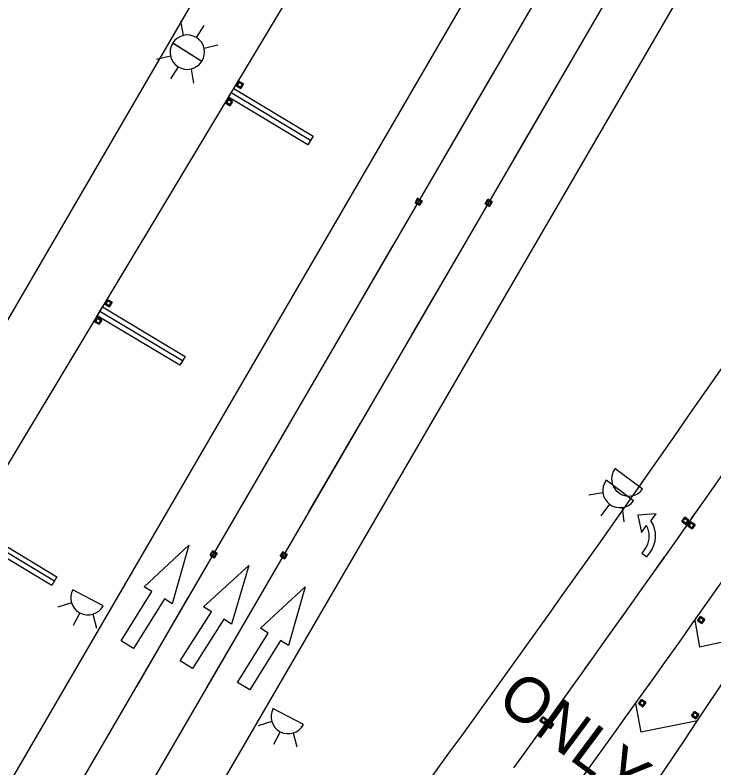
# Model space of a CAD drawing. Extents: x 2471014 to 2497726, y 6959577 to 6980268.
# Drawn here: x 2488749.7 to 2488886.8, y 6964487 to 6964634.8 of the extents above; entities that cross this region are included whole.
import ezdxf

# ---------------------------------------------------------------- set-up
doc = ezdxf.new("R2010")
doc.units = 0
for name, color, linetype in [('13', 7, 'Continuous'), ('18', 7, 'Continuous'), ('23', 7, 'Continuous'), ('25', 7, 'Continuous'), ('59', 7, 'Continuous'), ('ALIGN_ML_IH35_NB_SB', 7, 'Continuous'), ('G-GRID-MAJR', 7, 'Continuous'), ('Level 30', 7, 'Continuous'), ('Level 40', 7, 'Continuous'), ('p_structure fence', 7, 'Continuous'), ('p_structure wall', 7, 'Continuous'), ('PMK_Del_D-SW_SZ_TYC_CTB_BI', 7, 'Continuous'), ('PMK_Del_D-SY_SZ_TYC_CTB', 7, 'Continuous'), ('PMK_Pav_Marker_TY I C', 7, 'Continuous'), ('RDWY_PAVE_XSTREET_FOC', 7, 'Continuous'), ('S-BRDG-DECK', 7, 'Continuous'), ('SHADE SW', 7, 'Continuous'), ('V7_25', 7, 'Continuous')]:
    doc.layers.add(name, color=color, linetype=linetype)

msp = doc.modelspace()

# ---------------------------------------------------------------- linework, layer by layer
at = {"layer": '13'}
msp.add_line((2488620.75, 6964263.98), (2489501.89, 6965780.24), dxfattribs=at)
msp.add_arc((2485597.1, 6966838.82), 4000, 322.02534, 329.83805, dxfattribs=at)
at = {"layer": '18'}
for p, q in [((2488642.18, 6964392.39), (2489501.29, 6965870.76)), ((2488735.14, 6964389.16), (2489533.02, 6965762.15)), ((2488737.13, 6964527.93), (2489107.54, 6965145.42))]:
    msp.add_line(p, q, dxfattribs=at)
at = {"layer": '23'}
for p, q in [((2488828.16, 6964597.98), (2488828.67, 6964598.86)), ((2488829.54, 6964598.35), (2488828.67, 6964598.86)), ((2488828.67, 6964598.86), (2488828.72, 6964598.63)), ((2488828.72, 6964598.63), (2488828.84, 6964598.56)), ((2488828.84, 6964598.56), (2488829.3, 6964598.29)), ((2488841.91, 6964597.77), (2488842.42, 6964598.65)), ((2488843.3, 6964598.14), (2488842.42, 6964598.65)), ((2488842.42, 6964598.65), (2488842.47, 6964598.42)), ((2488828.38, 6964598.05), (2488828.16, 6964597.98)), ((2488828.16, 6964597.98), (2488828.39, 6964597.85)), ((2488828.96, 6964597.71), (2488828.38, 6964598.05)), ((2488828.39, 6964597.85), (2488829.03, 6964597.47)), ((2488829.03, 6964597.47), (2488828.96, 6964597.71)), ((2488829.54, 6964598.35), (2488829.03, 6964597.47)), ((2488829.3, 6964598.29), (2488829.54, 6964598.35)), ((2488842.13, 6964597.83), (2488841.91, 6964597.77)), ((2488841.91, 6964597.77), (2488842.14, 6964597.63)), ((2488842.72, 6964597.49), (2488842.13, 6964597.83)), ((2488842.14, 6964597.63), (2488842.79, 6964597.26)), ((2488842.47, 6964598.42), (2488842.6, 6964598.35)), ((2488842.6, 6964598.35), (2488843.06, 6964598.08)), ((2488842.79, 6964597.26), (2488842.72, 6964597.49)), ((2488843.3, 6964598.14), (2488842.79, 6964597.26)), ((2488843.06, 6964598.08), (2488843.3, 6964598.14)), ((2488880.46, 6964535.41), (2488881.04, 6964536.24)), ((2488880.68, 6964535.46), (2488880.46, 6964535.41)), ((2488880.46, 6964535.41), (2488880.68, 6964535.26)), ((2488881.24, 6964535.07), (2488880.68, 6964535.46)), ((2488880.68, 6964535.26), (2488881.29, 6964534.83)), ((2488881.87, 6964535.66), (2488881.04, 6964536.24)), ((2488881.04, 6964536.24), (2488881.07, 6964536.01)), ((2488881.07, 6964536.01), (2488881.19, 6964535.93)), ((2488881.19, 6964535.93), (2488881.63, 6964535.62)), ((2488881.29, 6964534.83), (2488881.24, 6964535.07)), ((2488881.87, 6964535.66), (2488881.29, 6964534.83)), ((2488881.63, 6964535.62), (2488881.87, 6964535.66)), ((2488881.67, 6964534.53), (2488882.25, 6964535.37)), ((2488883.08, 6964534.78), (2488882.25, 6964535.37)), ((2488882.25, 6964535.37), (2488882.29, 6964535.13)), ((2488882.29, 6964535.13), (2488882.4, 6964535.05)), ((2488882.4, 6964535.05), (2488882.84, 6964534.75)), ((2488881.9, 6964534.58), (2488881.67, 6964534.53)), ((2488881.67, 6964534.53), (2488881.89, 6964534.38)), ((2488881.89, 6964534.38), (2488882.5, 6964533.95)), ((2488882.45, 6964534.19), (2488881.9, 6964534.58)), ((2488882.5, 6964533.95), (2488882.45, 6964534.19)), ((2488883.08, 6964534.78), (2488882.5, 6964533.95)), ((2488882.84, 6964534.75), (2488883.08, 6964534.78)), ((2488787.96, 6964528.81), (2488788.47, 6964529.69)), ((2488789.35, 6964529.18), (2488788.47, 6964529.69)), ((2488788.47, 6964529.69), (2488788.52, 6964529.46)), ((2488788.52, 6964529.46), (2488788.65, 6964529.39)), ((2488788.65, 6964529.39), (2488789.11, 6964529.12)), ((2488789.35, 6964529.18), (2488788.84, 6964528.3)), ((2488789.11, 6964529.12), (2488789.35, 6964529.18)), ((2488801.71, 6964528.6), (2488802.23, 6964529.48)), ((2488803.1, 6964528.97), (2488802.23, 6964529.48)), ((2488802.23, 6964529.48), (2488802.28, 6964529.25)), ((2488802.28, 6964529.25), (2488802.4, 6964529.18)), ((2488802.4, 6964529.18), (2488802.86, 6964528.91)), ((2488788.18, 6964528.88), (2488787.96, 6964528.81)), ((2488787.96, 6964528.81), (2488788.19, 6964528.68)), ((2488788.77, 6964528.54), (2488788.18, 6964528.88)), ((2488788.19, 6964528.68), (2488788.84, 6964528.3)), ((2488788.84, 6964528.3), (2488788.77, 6964528.54)), ((2488801.94, 6964528.66), (2488801.71, 6964528.6)), ((2488801.71, 6964528.6), (2488801.95, 6964528.46)), ((2488802.52, 6964528.32), (2488801.94, 6964528.66)), ((2488801.95, 6964528.46), (2488802.59, 6964528.09)), ((2488802.59, 6964528.09), (2488802.52, 6964528.32)), ((2488803.1, 6964528.97), (2488802.59, 6964528.09)), ((2488802.86, 6964528.91), (2488803.1, 6964528.97)), ((2488883.58, 6964515.97), (2488884.16, 6964516.79)), ((2488883.81, 6964516.01), (2488883.58, 6964515.97)), ((2488883.58, 6964515.97), (2488883.8, 6964515.81)), ((2488883.8, 6964515.81), (2488884.41, 6964515.38)), ((2488884.36, 6964515.62), (2488883.81, 6964516.01)), ((2488884.99, 6964516.21), (2488884.16, 6964516.79)), ((2488884.16, 6964516.79), (2488884.2, 6964516.56)), ((2488884.2, 6964516.56), (2488884.31, 6964516.48)), ((2488884.31, 6964516.48), (2488884.75, 6964516.17)), ((2488884.99, 6964516.21), (2488884.41, 6964515.38)), ((2488884.75, 6964516.17), (2488884.99, 6964516.21)), ((2488884.41, 6964515.38), (2488884.36, 6964515.62)), ((2488872, 6964499.66), (2488872.59, 6964500.49)), ((2488872.22, 6964499.71), (2488872, 6964499.66)), ((2488872, 6964499.66), (2488872.21, 6964499.51)), ((2488872.21, 6964499.51), (2488872.82, 6964499.07)), ((2488872.77, 6964499.31), (2488872.22, 6964499.71)), ((2488873.41, 6964499.9), (2488872.59, 6964500.49)), ((2488872.59, 6964500.49), (2488872.62, 6964500.26)), ((2488872.62, 6964500.26), (2488872.73, 6964500.18)), ((2488872.73, 6964500.18), (2488873.17, 6964499.87)), ((2488873.41, 6964499.9), (2488872.82, 6964499.07)), ((2488873.17, 6964499.87), (2488873.41, 6964499.9)), ((2488872.82, 6964499.07), (2488872.77, 6964499.31)), ((2488882.38, 6964497.27), (2488882.94, 6964498.12)), ((2488883.79, 6964497.56), (2488882.94, 6964498.12)), ((2488882.94, 6964498.12), (2488882.98, 6964497.89)), ((2488852.66, 6964496.29), (2488853.25, 6964497.11)), ((2488854.07, 6964496.52), (2488853.25, 6964497.11)), ((2488853.25, 6964497.11), (2488853.28, 6964496.88)), ((2488853.28, 6964496.88), (2488853.4, 6964496.8)), ((2488853.4, 6964496.8), (2488853.83, 6964496.49)), ((2488882.61, 6964497.33), (2488882.38, 6964497.27)), ((2488882.38, 6964497.27), (2488882.6, 6964497.12)), ((2488882.6, 6964497.12), (2488883.23, 6964496.71)), ((2488883.17, 6964496.95), (2488882.61, 6964497.33)), ((2488882.98, 6964497.89), (2488883.1, 6964497.81)), ((2488883.1, 6964497.81), (2488883.54, 6964497.52)), ((2488883.23, 6964496.71), (2488883.17, 6964496.95)), ((2488883.79, 6964497.56), (2488883.23, 6964496.71)), ((2488883.54, 6964497.52), (2488883.79, 6964497.56)), ((2488852.89, 6964496.33), (2488852.66, 6964496.29)), ((2488852.66, 6964496.29), (2488852.88, 6964496.13)), ((2488852.88, 6964496.13), (2488853.48, 6964495.7)), ((2488853.44, 6964495.94), (2488852.89, 6964496.33)), ((2488853.48, 6964495.7), (2488853.44, 6964495.94)), ((2488854.07, 6964496.52), (2488853.48, 6964495.7)), ((2488853.83, 6964496.49), (2488854.07, 6964496.52)), ((2488853.87, 6964495.41), (2488854.47, 6964496.23)), ((2488854.1, 6964495.45), (2488853.87, 6964495.41)), ((2488853.87, 6964495.41), (2488854.09, 6964495.25)), ((2488854.09, 6964495.25), (2488854.7, 6964494.82)), ((2488854.65, 6964495.06), (2488854.1, 6964495.45)), ((2488855.29, 6964495.64), (2488854.47, 6964496.23)), ((2488854.47, 6964496.23), (2488854.5, 6964496)), ((2488854.5, 6964496), (2488854.61, 6964495.92)), ((2488854.61, 6964495.92), (2488855.05, 6964495.61)), ((2488854.7, 6964494.82), (2488854.65, 6964495.06)), ((2488855.29, 6964495.64), (2488854.7, 6964494.82)), ((2488855.05, 6964495.61), (2488855.29, 6964495.64))]:
    msp.add_line(p, q, dxfattribs=at)
for points in [[(2488828.38, 6964598.05), (2488828.72, 6964598.63), (2488829.3, 6964598.29), (2488828.96, 6964597.71)], [(2488842.13, 6964597.83), (2488842.47, 6964598.42), (2488843.06, 6964598.08), (2488842.72, 6964597.49)], [(2488880.68, 6964535.46), (2488881.07, 6964536.01), (2488881.63, 6964535.62), (2488881.24, 6964535.07)], [(2488881.9, 6964534.58), (2488882.29, 6964535.13), (2488882.84, 6964534.75), (2488882.45, 6964534.19)], [(2488788.18, 6964528.88), (2488788.52, 6964529.46), (2488789.11, 6964529.12), (2488788.77, 6964528.54)], [(2488801.94, 6964528.66), (2488802.28, 6964529.25), (2488802.86, 6964528.91), (2488802.52, 6964528.32)], [(2488883.81, 6964516.01), (2488884.2, 6964516.56), (2488884.75, 6964516.17), (2488884.36, 6964515.62)], [(2488872.22, 6964499.71), (2488872.62, 6964500.26), (2488873.17, 6964499.87), (2488872.77, 6964499.31)], [(2488852.89, 6964496.33), (2488853.28, 6964496.88), (2488853.83, 6964496.49), (2488853.44, 6964495.94)], [(2488882.61, 6964497.33), (2488882.98, 6964497.89), (2488883.54, 6964497.52), (2488883.17, 6964496.95)], [(2488854.1, 6964495.45), (2488854.5, 6964496), (2488855.05, 6964495.61), (2488854.65, 6964495.06)]]:
    msp.add_lwpolyline(points, close=True, dxfattribs=at)
at = {"layer": '25'}
for centre, radius, start, end in [((2485597.1, 6966838.82), 4024, 324.04653, 328.03154), ((2487228.94, 6965594.72), 1986, 322.75841, 329.83805), ((2487228.94, 6965594.72), 2000, 322.75857, 329.83805)]:
    msp.add_arc(centre, radius, start, end, dxfattribs=at)
at = {"layer": '59'}
msp.add_arc((2485597.1, 6966838.82), 4012, 324.11333, 329.83805, dxfattribs=at)
at = {"layer": 'ALIGN_ML_IH35_NB_SB'}
for p, q in [((2488775.04, 6964522.61), (2488783.81, 6964530.79)), ((2488783.81, 6964530.79), (2488780.52, 6964519.27)), ((2488786.69, 6964518.65), (2488795.54, 6964526.75)), ((2488795.54, 6964526.75), (2488792.14, 6964515.26)), ((2488770.55, 6964512.01), (2488776.56, 6964521.66)), ((2488776.56, 6964521.66), (2488775.04, 6964522.61)), ((2488797.83, 6964514.45), (2488806.61, 6964522.62)), ((2488806.61, 6964522.62), (2488803.31, 6964511.1)), ((2488778.99, 6964520.22), (2488772.95, 6964510.52)), ((2488780.52, 6964519.27), (2488778.99, 6964520.22)), ((2488782.11, 6964508.09), (2488788.21, 6964517.69)), ((2488788.21, 6964517.69), (2488786.69, 6964518.65)), ((2488790.63, 6964516.22), (2488784.49, 6964506.58)), ((2488792.14, 6964515.26), (2488790.63, 6964516.22)), ((2488799.36, 6964513.5), (2488797.83, 6964514.45)), ((2488793.34, 6964503.85), (2488799.36, 6964513.5)), ((2488772.95, 6964510.52), (2488770.55, 6964512.01)), ((2488801.78, 6964512.06), (2488795.73, 6964502.36)), ((2488803.31, 6964511.1), (2488801.78, 6964512.06)), ((2488784.49, 6964506.58), (2488782.11, 6964508.09)), ((2488795.73, 6964502.36), (2488793.34, 6964503.85))]:
    msp.add_line(p, q, dxfattribs=at)
at = {"layer": 'G-GRID-MAJR'}
for p, q in [((2488791.57, 6964618.68), (2488792.6, 6964620.4)), ((2488792.6, 6964620.4), (2488808.19, 6964611.04)), ((2488807.16, 6964609.33), (2488791.57, 6964618.68)), ((2488808.19, 6964611.04), (2488807.16, 6964609.33)), ((2488765.85, 6964575.8), (2488766.88, 6964577.52)), ((2488766.88, 6964577.52), (2488783.07, 6964567.81)), ((2488782.04, 6964566.09), (2488765.85, 6964575.8)), ((2488783.07, 6964567.81), (2488782.04, 6964566.09)), ((2488741.16, 6964534.64), (2488757.94, 6964524.57)), ((2488756.91, 6964522.86), (2488740.13, 6964532.93)), ((2488757.94, 6964524.57), (2488756.91, 6964522.86)), ((2488883, 6964516.02), (2488883.97, 6964510.77)), ((2488894.52, 6964513.02), (2488883.97, 6964510.77)), ((2488871.41, 6964499.71), (2488872.43, 6964494.05)), ((2488883.55, 6964496.3), (2488872.43, 6964494.05))]:
    msp.add_line(p, q, dxfattribs=at)
at = {"layer": 'Level 30'}
for p, q in [((2488806.26, 6964495.56), (2488800.29, 6964498.72)), ((2488800.05, 6964496.15), (2488797.37, 6964495.29)), ((2488801.7, 6964494.16), (2488800.38, 6964491.67)), ((2488804.27, 6964493.92), (2488804.99, 6964491.2))]:
    msp.add_line(p, q, dxfattribs=at)
msp.add_arc((2488803.28, 6964497.14), 3.37, 152.0959, 332.0959, dxfattribs=at)
at = {"layer": 'Level 40'}
for p, q in [((2488882.34, 6964535.92), (2488884.06, 6964538.38)), ((2488875.43, 6964526.11), (2488877.16, 6964528.56)), ((2488868.5, 6964516.31), (2488870.24, 6964518.76)), ((2488861.54, 6964506.54), (2488863.28, 6964508.98)), ((2488854.55, 6964496.78), (2488856.3, 6964499.22)), ((2488847.53, 6964487.05), (2488849.29, 6964489.48))]:
    msp.add_line(p, q, dxfattribs=at)
at = {"layer": 'p_structure wall'}
for p, q in [((2488875.47, 6964536.94), (2488871.87, 6964536.69)), ((2488871.87, 6964536.69), (2488872.57, 6964533.27)), ((2488874.43, 6964535.57), (2488875.47, 6964536.94)), ((2488872.57, 6964533.27), (2488873.58, 6964534.6)), ((2488873.23, 6964530), (2488872.63, 6964529.21)), ((2488872.63, 6964529.21), (2488873.61, 6964528.47)), ((2488873.61, 6964528.47), (2488874.21, 6964529.25))]:
    msp.add_line(p, q, dxfattribs=at)
for radius, start, end in [(5.49, 322.8479, 33.1373), (4.26, 330.7191, 28.4617), (4.26, 322.889, 328.4717), (4.26, 328.4717, 330.7191)]:
    msp.add_arc((2488869.83, 6964532.57), radius, start, end, dxfattribs=at)
at = {"layer": 'PMK_Del_D-SW_SZ_TYC_CTB_BI'}
for p, q in [((2488782.74, 6964630.82), (2488782.22, 6964633.59)), ((2488785.29, 6964630.39), (2488786.79, 6964632.77)), ((2488786.33, 6964625.72), (2488780.62, 6964629.32)), ((2488780.63, 6964629.33), (2488786.34, 6964625.73)), ((2488786.78, 6964628.28), (2488789.51, 6964628.94)), ((2488780.18, 6964626.77), (2488777.45, 6964626.11)), ((2488781.68, 6964624.66), (2488780.18, 6964622.28)), ((2488784.22, 6964624.22), (2488784.74, 6964621.46))]:
    msp.add_line(p, q, dxfattribs=at)
for centre, start, end in [((2488783.49, 6964627.53), 327.7622, 147.7622), ((2488783.48, 6964627.52), 147.7622, 327.7622)]:
    msp.add_arc(centre, 3.37, start, end, dxfattribs=at)
at = {"layer": 'PMK_Del_D-SY_SZ_TYC_CTB'}
for p, q in [((2488766.98, 6964518.86), (2488761.02, 6964522.03)), ((2488760.77, 6964519.46), (2488758.09, 6964518.6)), ((2488762.41, 6964517.47), (2488761.09, 6964514.98)), ((2488764.98, 6964517.22), (2488765.7, 6964514.5))]:
    msp.add_line(p, q, dxfattribs=at)
msp.add_arc((2488764, 6964520.44), 3.37, 151.9258, 331.9258, dxfattribs=at)
at = {"layer": 'PMK_Pav_Marker_TY I C'}
for p, q in [((2488793.1, 6964620.95), (2488793.63, 6964621.81)), ((2488793.32, 6964621.01), (2488793.1, 6964620.95)), ((2488793.1, 6964620.95), (2488793.33, 6964620.81)), ((2488793.9, 6964620.65), (2488793.32, 6964621.01)), ((2488793.33, 6964620.81), (2488793.96, 6964620.42)), ((2488794.49, 6964621.28), (2488793.63, 6964621.81)), ((2488793.63, 6964621.81), (2488793.68, 6964621.58)), ((2488793.68, 6964621.58), (2488793.8, 6964621.51)), ((2488793.8, 6964621.51), (2488794.25, 6964621.23)), ((2488793.96, 6964620.42), (2488793.9, 6964620.65)), ((2488794.49, 6964621.28), (2488793.96, 6964620.42)), ((2488794.25, 6964621.23), (2488794.49, 6964621.28)), ((2488791, 6964617.54), (2488791.53, 6964618.41)), ((2488792.39, 6964617.87), (2488791.53, 6964618.41)), ((2488791.53, 6964618.41), (2488791.58, 6964618.18)), ((2488791.58, 6964618.18), (2488791.7, 6964618.1)), ((2488791.7, 6964618.1), (2488792.15, 6964617.82)), ((2488792.39, 6964617.87), (2488791.86, 6964617.01)), ((2488792.15, 6964617.82), (2488792.39, 6964617.87)), ((2488791.22, 6964617.6), (2488791, 6964617.54)), ((2488791, 6964617.54), (2488791.23, 6964617.4)), ((2488791.8, 6964617.25), (2488791.22, 6964617.6)), ((2488791.23, 6964617.4), (2488791.86, 6964617.01)), ((2488791.86, 6964617.01), (2488791.8, 6964617.25)), ((2488767.35, 6964578.08), (2488767.86, 6964578.95)), ((2488767.57, 6964578.14), (2488767.35, 6964578.08)), ((2488767.35, 6964578.08), (2488767.58, 6964577.94)), ((2488768.15, 6964577.8), (2488767.57, 6964578.14)), ((2488767.58, 6964577.94), (2488768.22, 6964577.57)), ((2488768.73, 6964578.44), (2488767.86, 6964578.95)), ((2488767.86, 6964578.95), (2488767.91, 6964578.73)), ((2488767.91, 6964578.73), (2488768.03, 6964578.65)), ((2488768.03, 6964578.65), (2488768.49, 6964578.38)), ((2488768.22, 6964577.57), (2488768.15, 6964577.8)), ((2488768.73, 6964578.44), (2488768.22, 6964577.57)), ((2488768.49, 6964578.38), (2488768.73, 6964578.44)), ((2488765.32, 6964574.63), (2488765.83, 6964575.5)), ((2488766.71, 6964574.99), (2488765.83, 6964575.5)), ((2488765.83, 6964575.5), (2488765.89, 6964575.28)), ((2488765.89, 6964575.28), (2488766.01, 6964575.2)), ((2488766.01, 6964575.2), (2488766.47, 6964574.93)), ((2488766.71, 6964574.99), (2488766.19, 6964574.12)), ((2488766.47, 6964574.93), (2488766.71, 6964574.99)), ((2488765.54, 6964574.69), (2488765.32, 6964574.63)), ((2488765.32, 6964574.63), (2488765.55, 6964574.49)), ((2488766.13, 6964574.35), (2488765.54, 6964574.69)), ((2488765.55, 6964574.49), (2488766.19, 6964574.12)), ((2488766.19, 6964574.12), (2488766.13, 6964574.35))]:
    msp.add_line(p, q, dxfattribs=at)
for points in [[(2488793.32, 6964621.01), (2488793.68, 6964621.58), (2488794.25, 6964621.23), (2488793.9, 6964620.65)], [(2488791.22, 6964617.6), (2488791.58, 6964618.18), (2488792.15, 6964617.82), (2488791.8, 6964617.25)], [(2488767.57, 6964578.14), (2488767.91, 6964578.73), (2488768.49, 6964578.38), (2488768.15, 6964577.8)], [(2488765.54, 6964574.69), (2488765.89, 6964575.28), (2488766.47, 6964574.93), (2488766.13, 6964574.35)]]:
    msp.add_lwpolyline(points, close=True, dxfattribs=at)
at = {"layer": 'RDWY_PAVE_XSTREET_FOC'}
for p, q in [((2488833.87, 6964606.82), (2488843.91, 6964624.11)), ((2488847.62, 6964606.6), (2488857.67, 6964623.89)), ((2488813.77, 6964572.23), (2488823.82, 6964589.53)), ((2488827.52, 6964572.02), (2488837.57, 6964589.31)), ((2488793.67, 6964537.65), (2488803.72, 6964554.94)), ((2488807.42, 6964537.43), (2488817.47, 6964554.73)), ((2488773.57, 6964503.06), (2488783.62, 6964520.36)), ((2488787.33, 6964502.85), (2488797.38, 6964520.14))]:
    msp.add_line(p, q, dxfattribs=at)
at = {"layer": 'S-BRDG-DECK'}
for p, q in [((2488737.13, 6964527.93), (2489107.54, 6965145.42)), ((2488807.68, 6964610.18), (2488792.08, 6964619.54)), ((2488782.55, 6964566.95), (2488766.36, 6964576.66)), ((2488757.43, 6964523.71), (2488740.64, 6964533.78))]:
    msp.add_line(p, q, dxfattribs=at)
at = {"layer": 'SHADE SW'}
for p, q in [((2488872.77, 6964541.74), (2488867.37, 6964545.79)), ((2488871.03, 6964539.47), (2488865.63, 6964543.53)), ((2488864.99, 6964541.03), (2488862.21, 6964540.59)), ((2488866.3, 6964538.8), (2488864.61, 6964536.56)), ((2488868.8, 6964538.16), (2488869.09, 6964535.36))]:
    msp.add_line(p, q, dxfattribs=at)
for centre in [(2488870.07, 6964543.77), (2488868.33, 6964541.5)]:
    msp.add_arc(centre, 3.37, 143.0592, 323.0592, dxfattribs=at)
at = {"layer": 'V7_25'}
for p, q in [((2488631.13, 6964257.95), (2489512.27, 6965774.21)), ((2488641.5, 6964251.92), (2489522.64, 6965768.18))]:
    msp.add_line(p, q, dxfattribs=at)

# ---------------------------------------------------------------- texts
at = {"layer": 'p_structure fence'}
msp.add_text('ONLY', height=8.898, rotation=323.3483, dxfattribs=at).set_placement((2488843.81, 6964499.56))

doc.saveas('drawing.dxf')
